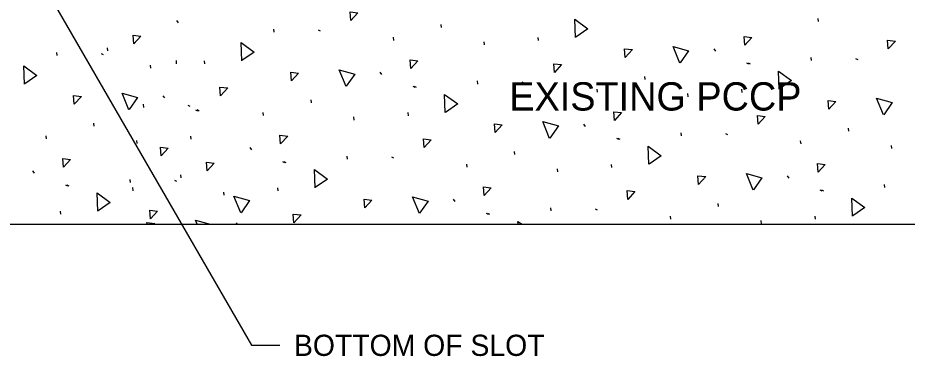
# Model space of a CAD drawing. Extents: x 49991.4 to 50021, y 49987.6 to 50011.4.
# Drawn here: x 50011.101 to 50013.616, y 49992.21 to 49993.167 of the extents above; entities that cross this region are included whole.
import ezdxf

# ---------------------------------------------------------------- set-up
doc = ezdxf.new("R2010")
doc.units = 0
for name, color, linetype in [('Level 1', 7, 'Continuous'), ('Level 2', 7, 'Continuous'), ('Level 3', 7, 'Continuous'), ('Level 4', 7, 'Continuous')]:
    doc.layers.add(name, color=color, linetype=linetype)

msp = doc.modelspace()

# ---------------------------------------------------------------- linework, layer by layer
at = {"layer": 'Level 1'}
msp.add_lwpolyline([(50001.9803, 49992.5827), (50004.606, 49992.5827), (50014.3713, 49992.5827)], dxfattribs=at)
at = {"layer": 'Level 3'}
for p, q in [((50011.1581, 49993.2857), (50011.7617, 49992.2404)), ((50011.7617, 49992.2404), (50011.8417, 49992.2404))]:
    msp.add_line(p, q, dxfattribs=at)
at = {"layer": 'Level 4'}
for p, q in [((50011.5491, 49993.1592), (50011.5539, 49993.1527)), ((50013.3649, 49993.1564), (50013.364, 49993.1651)), ((50011.8258, 49993.1262), (50011.8249, 49993.1349)), ((50012.2993, 49993.1391), (50012.2984, 49993.1478)), ((50011.9503, 49993.1325), (50011.9561, 49993.1296)), ((50012.1642, 49993.1031), (50012.1633, 49993.1118)), ((50012.5736, 49993.1026), (50012.5727, 49993.1113)), ((50012.4208, 49993.0903), (50012.4198, 49993.099)), ((50011.2116, 49993.0601), (50011.2107, 49993.0688)), ((50011.3362, 49993.0663), (50011.3419, 49993.0635)), ((50011.3551, 49993.073), (50011.3542, 49993.0817)), ((50013.0691, 49993.0788), (50013.0738, 49993.0723)), ((50011.4766, 49993.0242), (50011.4757, 49993.0329)), ((50011.55, 49993.037), (50011.5491, 49993.0457)), ((50011.6295, 49993.0364), (50011.6285, 49993.0451)), ((50013.1619, 49993.0392), (50013.1676, 49993.0364)), ((50013.166, 49993.0392), (50013.1717, 49993.0364)), ((50013.3458, 49993.0458), (50013.3449, 49993.0545)), ((50013.4703, 49993.0521), (50013.4761, 49993.0492)), ((50012.1249, 49993.0127), (50012.1296, 49993.0062)), ((50012.4016, 49992.9796), (50012.4007, 49992.9883)), ((50012.5261, 49992.9859), (50012.5319, 49992.9831)), ((50012.8751, 49992.9925), (50012.8741, 49993.0012)), ((50012.2177, 49992.9731), (50012.2235, 49992.9702)), ((50012.2218, 49992.9731), (50012.2276, 49992.9703)), ((50012.74, 49992.9566), (50012.739, 49992.9653)), ((50013.1494, 49992.956), (50013.1485, 49992.9647)), ((50011.5107, 49992.9465), (50011.5155, 49992.9401)), ((50011.9309, 49992.9264), (50011.93, 49992.9351)), ((50012.9966, 49992.9437), (50012.9956, 49992.9524)), ((50011.4574, 49992.9135), (50011.4565, 49992.9222)), ((50011.582, 49992.9198), (50011.5877, 49992.9169)), ((50011.6035, 49992.9069), (50011.6093, 49992.9041)), ((50011.6076, 49992.907), (50011.6134, 49992.9041)), ((50011.7958, 49992.8905), (50011.7949, 49992.8992)), ((50012.0524, 49992.8776), (50012.0515, 49992.8863)), ((50012.2053, 49992.8899), (50012.2043, 49992.8986)), ((50011.3167, 49992.8603), (50011.3158, 49992.869)), ((50012.7007, 49992.8661), (50012.7054, 49992.8596)), ((50011.1816, 49992.8243), (50011.1807, 49992.833)), ((50011.5911, 49992.8237), (50011.5902, 49992.8324)), ((50012.9774, 49992.8331), (50012.9765, 49992.8418)), ((50013.1019, 49992.8394), (50013.1077, 49992.8365)), ((50013.4509, 49992.846), (50013.4499, 49992.8547)), ((50011.4382, 49992.8115), (50011.4373, 49992.8202)), ((50012.7935, 49992.8265), (50012.7993, 49992.8237)), ((50012.7976, 49992.8265), (50012.8034, 49992.8237)), ((50013.3158, 49992.81), (50013.3148, 49992.8187)), ((50013.5723, 49992.7972), (50013.5714, 49992.8059)), ((50011.7565, 49992.8), (50011.7613, 49992.7935)), ((50012.5067, 49992.7799), (50012.5058, 49992.7886)), ((50011.8493, 49992.7604), (50011.8551, 49992.7576)), ((50011.8534, 49992.7604), (50011.8592, 49992.7576)), ((50012.0332, 49992.767), (50012.0323, 49992.7757)), ((50012.1578, 49992.7732), (50012.1635, 49992.7704)), ((50011.1423, 49992.7338), (50011.1471, 49992.7274)), ((50012.3716, 49992.7439), (50012.3707, 49992.7526)), ((50012.6282, 49992.7311), (50012.6273, 49992.7398)), ((50012.7811, 49992.7433), (50012.7801, 49992.752)), ((50011.419, 49992.7008), (50011.4181, 49992.7095)), ((50011.5436, 49992.7071), (50011.5493, 49992.7043)), ((50011.5625, 49992.7137), (50011.5616, 49992.7224)), ((50013.2765, 49992.7196), (50013.2812, 49992.7131)), ((50011.2352, 49992.6943), (50011.2409, 49992.6914)), ((50011.2393, 49992.6943), (50011.245, 49992.6914)), ((50011.4274, 49992.6778), (50011.4265, 49992.6865)), ((50011.8369, 49992.6772), (50011.836, 49992.6859)), ((50013.3693, 49992.68), (50013.3751, 49992.6771)), ((50013.3734, 49992.68), (50013.3791, 49992.6772)), ((50013.5532, 49992.6865), (50013.5523, 49992.6952)), ((50011.684, 49992.6649), (50011.6831, 49992.6736)), ((50012.3323, 49992.6534), (50012.3371, 49992.6469)), ((50013.0825, 49992.6333), (50013.0816, 49992.642)), ((50011.2227, 49992.611), (50011.2218, 49992.6197)), ((50012.4251, 49992.6138), (50012.4309, 49992.611)), ((50012.4292, 49992.6139), (50012.435, 49992.611)), ((50012.609, 49992.6204), (50012.6081, 49992.6291)), ((50012.7335, 49992.6267), (50012.7393, 49992.6238)), ((50012.9474, 49992.5974), (50012.9465, 49992.606)), ((50013.3568, 49992.5968), (50013.3559, 49992.6055)), ((50011.7181, 49992.5873), (50011.7215, 49992.5827)), ((50013.204, 49992.5845), (50013.203, 49992.5932))]:
    msp.add_line(p, q, dxfattribs=at)
for points in [[(50012.0426, 49993.1591), (50012.0408, 49993.1837), (50012.0628, 49993.181), (50012.0426, 49993.1591)], [(50012.6781, 49993.1116), (50012.6763, 49993.1628), (50012.7133, 49993.136), (50012.6789, 49993.1121)], [(50011.4285, 49993.093), (50011.4266, 49993.1175), (50011.4486, 49993.1149), (50011.4285, 49993.093)], [(50013.1565, 49993.0894), (50013.1546, 49993.114), (50013.1767, 49993.1113), (50013.1565, 49993.0894)], [(50011.734, 49993.0455), (50011.7321, 49993.0967), (50011.7691, 49993.0699), (50011.7347, 49993.0459)], [(50012.9732, 49993.0386), (50012.9539, 49993.0861), (50012.9979, 49993.0735), (50012.9738, 49993.0393)], [(50013.5626, 49993.0787), (50013.5607, 49993.1032), (50013.5828, 49993.1006), (50013.5626, 49993.0787)], [(50012.8188, 49993.0549), (50012.8169, 49993.0795), (50012.8389, 49993.0768), (50012.8188, 49993.0549)], [(50012.2123, 49993.0233), (50012.2105, 49993.0478), (50012.2325, 49993.0452), (50012.2123, 49993.0233)], [(50012.6184, 49993.0125), (50012.6166, 49993.0371), (50012.6386, 49993.0344), (50012.6184, 49993.0125)], [(50011.1198, 49992.9794), (50011.1179, 49993.0306), (50011.1549, 49993.0037), (50011.1206, 49992.9798)], [(50011.8746, 49992.9888), (50011.8727, 49993.0133), (50011.8947, 49993.0107), (50011.8746, 49992.9888)], [(50012.029, 49992.9725), (50012.0098, 49993.02), (50012.0537, 49993.0074), (50012.0296, 49992.9732)], [(50013.2539, 49992.9651), (50013.2521, 49993.0163), (50013.2891, 49992.9895), (50013.2547, 49992.9655)], [(50011.6743, 49992.9464), (50011.6724, 49992.971), (50011.6944, 49992.9683), (50011.6743, 49992.9464)], [(50011.2604, 49992.9226), (50011.2585, 49992.9472), (50011.2806, 49992.9445), (50011.2604, 49992.9226)], [(50011.4149, 49992.9063), (50011.3956, 49992.9538), (50011.4395, 49992.9413), (50011.4154, 49992.907)], [(50012.3098, 49992.8989), (50012.3079, 49992.9501), (50012.3449, 49992.9233), (50012.3105, 49992.8994)], [(50013.3946, 49992.9084), (50013.3927, 49992.9329), (50013.4147, 49992.9303), (50013.3946, 49992.9084)], [(50013.549, 49992.8921), (50013.5297, 49992.9395), (50013.5737, 49992.927), (50013.5496, 49992.8927)], [(50012.7881, 49992.8767), (50012.7863, 49992.9013), (50012.8083, 49992.8986), (50012.7881, 49992.8767)], [(50013.1942, 49992.866), (50013.1924, 49992.8906), (50013.2144, 49992.8879), (50013.1942, 49992.866)], [(50012.4504, 49992.8422), (50012.4485, 49992.8668), (50012.4705, 49992.8641), (50012.4504, 49992.8422)], [(50012.6048, 49992.8259), (50012.5856, 49992.8734), (50012.6295, 49992.8609), (50012.6054, 49992.8266)], [(50011.844, 49992.8106), (50011.8421, 49992.8352), (50011.8641, 49992.8325), (50011.844, 49992.8106)], [(50012.2501, 49992.7999), (50012.2482, 49992.8244), (50012.2702, 49992.8218), (50012.2501, 49992.7999)], [(50011.5062, 49992.7761), (50011.5043, 49992.8006), (50011.5264, 49992.798), (50011.5062, 49992.7761)], [(50012.8856, 49992.7524), (50012.8837, 49992.8036), (50012.9207, 49992.7768), (50012.8863, 49992.7528)], [(50011.2298, 49992.7445), (50011.2279, 49992.769), (50011.2499, 49992.7664), (50011.2298, 49992.7445)], [(50011.6359, 49992.7337), (50011.634, 49992.7583), (50011.656, 49992.7556), (50011.6359, 49992.7337)], [(50011.9414, 49992.6862), (50011.9395, 49992.7375), (50011.9765, 49992.7106), (50011.9421, 49992.6867)], [(50013.3639, 49992.7302), (50013.362, 49992.7547), (50013.3841, 49992.7521), (50013.3639, 49992.7302)], [(50013.0262, 49992.6957), (50013.0243, 49992.7202), (50013.0463, 49992.7176), (50013.0262, 49992.6957)], [(50013.1806, 49992.6794), (50013.1613, 49992.7268), (50013.2053, 49992.7143), (50013.1812, 49992.68)], [(50012.4197, 49992.664), (50012.4179, 49992.6886), (50012.4399, 49992.6859), (50012.4197, 49992.664)], [(50011.3272, 49992.6201), (50011.3253, 49992.6713), (50011.3623, 49992.6445), (50011.328, 49992.6206)], [(50011.7314, 49992.6147), (50011.7121, 49992.6622), (50011.7561, 49992.6496), (50011.732, 49992.6154)], [(50012.2365, 49992.6132), (50012.2172, 49992.6607), (50012.2611, 49992.6482), (50012.237, 49992.6139)], [(50012.8258, 49992.6533), (50012.824, 49992.6779), (50012.846, 49992.6752), (50012.8258, 49992.6533)], [(50013.4613, 49992.6058), (50013.4595, 49992.657), (50013.4965, 49992.6302), (50013.4621, 49992.6063)], [(50012.082, 49992.6295), (50012.0801, 49992.6541), (50012.1022, 49992.6514), (50012.082, 49992.6295)], [(50011.4756, 49992.5979), (50011.4737, 49992.6225), (50011.4957, 49992.6198), (50011.4756, 49992.5979)], [(50011.8817, 49992.5872), (50011.8798, 49992.6117), (50011.9018, 49992.6091), (50011.8817, 49992.5872)], [(50011.4663, 49992.5827), (50011.4659, 49992.588), (50011.488, 49992.5853), (50011.4856, 49992.5827)], [(50011.6078, 49992.5827), (50011.603, 49992.5946), (50011.6447, 49992.5827)], [(50012.5156, 49992.5827), (50012.5153, 49992.5909), (50012.5267, 49992.5827)]]:
    msp.add_lwpolyline(points, dxfattribs=at)

# ---------------------------------------------------------------- texts
at = {"layer": 'Level 2'}
for s, height, p in [('EXISTING PCCP', 0.08, (50012.4908, 49992.9045)), ('BOTTOM OF SLOT ', 0.06, (50011.8817, 49992.2104))]:
    msp.add_text(s, height=height, dxfattribs=at).set_placement(p)

doc.saveas('drawing.dxf')
